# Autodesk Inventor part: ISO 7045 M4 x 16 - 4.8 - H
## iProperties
Created: 2002-11
Part Number: ISO 7045 M4 x 16 - 4.8 - H
Material: Standard
Catalog Web Link: file:///C:/Programme/Autodesk/Inventor%205.3/Content/Din/index.htm?doNavigateId=7A3AD77C-C431-11D4-A9F1-0080AD303E0A|31199DAEB16811D4BA6900C04F798F98|true
Description: Flachkopfschraube mit Kreuzschlitz
Document SubType Name: Standard Catalog Part
Standard: ISO 7045 M4 x 16 - 4.8 - H
Designer: Administrator
Control State: 0
Master: False
Checked Out: False
Shininess: 20.0
Angle Display Precision: 2
Document Length Units: 11269
Document Angle Units: 11279
Document Time Units: 11290
Document Mass Units: 11283
Document Length Units Precision: 3
Document Angle Units Precision: 2
Compacted: True
KLASSIFIKATION: 31161501 un/spsc
HERSTELLER: DIN Normsystem
Density: 0.0
Volumn: 0.0
Area: 0.0
PropertySet Name: Model Information
Author: Administrator
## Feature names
1. Basis1
